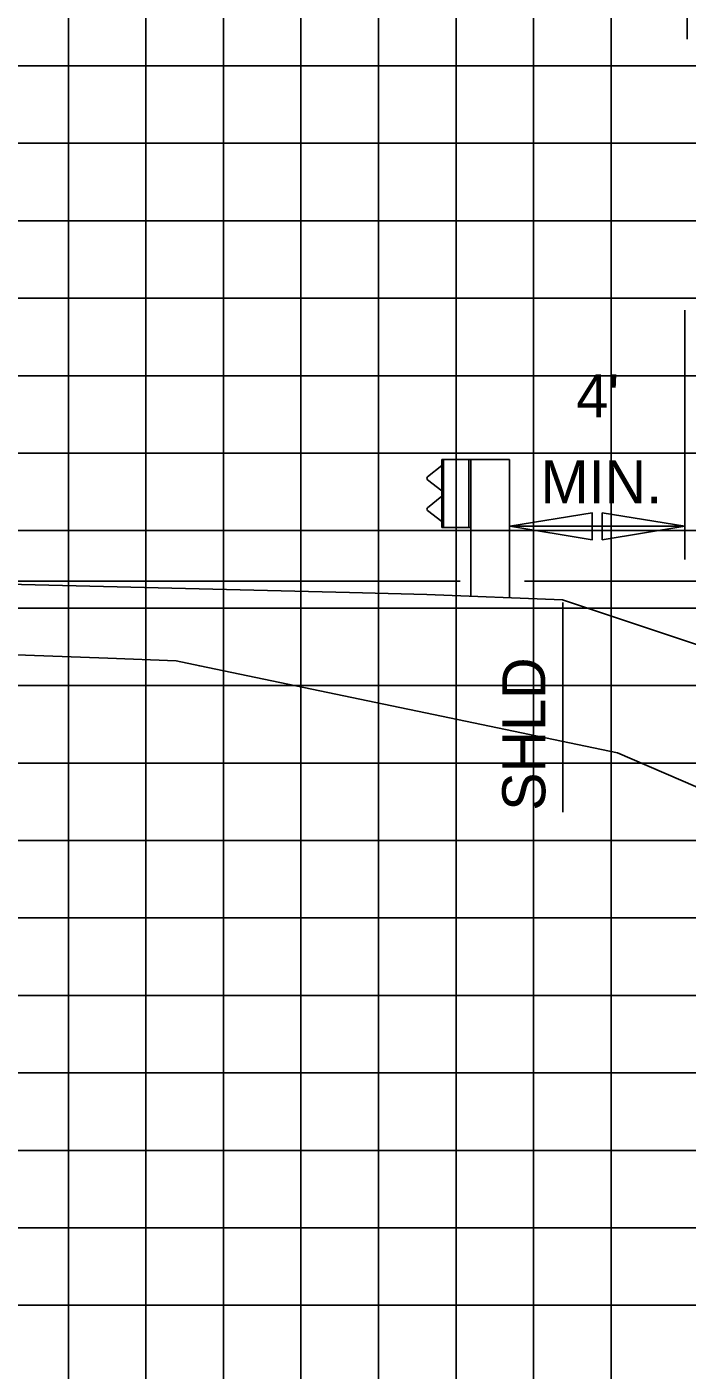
# Model space of a CAD drawing. Extents: x 2193008 to 2198143, y 1236112 to 1237864.
# Drawn here: x 2195451.71 to 2195468.75, y 1237175.43 to 1237210.11 of the extents above; entities that cross this region are included whole.
import ezdxf

# ---------------------------------------------------------------- set-up
doc = ezdxf.new("R2010")
doc.units = 0
for name, color, linetype in [('3', 7, 'Continuous'), ('60', 7, 'Continuous'), ('GSDIMS', 7, 'Continuous'), ('Level 1', 7, 'Continuous'), ('Level 55', 7, 'Continuous'), ('Level 61', 7, 'Continuous'), ('M-ROADS', 7, 'Continuous')]:
    doc.layers.add(name, color=color, linetype=linetype)

msp = doc.modelspace()

# ---------------------------------------------------------------- linework, layer by layer
at = {"layer": '3'}
msp.add_line((2195468.685, 1237196.363), (2195468.685, 1237202.8), dxfattribs=at)
at = {"layer": '60'}
msp.add_lwpolyline([(2195388.783, 1237193.146), (2195389.871, 1237193.142), (2195390.033, 1237193.15), (2195400.033, 1237193.607), (2195412.033, 1237194.155), (2195424.033, 1237194.703), (2195436.033, 1237195.252), (2195448.033, 1237195.8), (2195460.033, 1237195.509), (2195462.033, 1237195.46), (2195465.533, 1237195.32), (2195498.642, 1237184.284)], dxfattribs=at)
at = {"layer": 'GSDIMS'}
for p, q in [((2195468.745, 1237209.793), (2195468.745, 1237211.535)), ((2195462.887, 1237195.8), (2195448.033, 1237195.8)), ((2195470.334, 1237195.8), (2195464.548, 1237195.8)), ((2195465.539, 1237189.836), (2195465.539, 1237195.251))]:
    msp.add_line(p, q, dxfattribs=at)
for points in [[(2195464.17, 1237197.218), (2195466.299, 1237196.87), (2195466.299, 1237197.565)], [(2195468.685, 1237197.218), (2195466.557, 1237196.87), (2195466.557, 1237197.565)]]:
    msp.add_lwpolyline(points, close=True, dxfattribs=at)
at = {"layer": 'Level 1'}
for p, q in [((2195462.414, 1237198.79), (2195462.048, 1237198.491)), ((2195462.414, 1237198.94), (2195462.414, 1237197.19)), ((2195464.164, 1237198.94), (2195462.414, 1237198.94)), ((2195462.464, 1237198.94), (2195462.464, 1237197.19)), ((2195463.114, 1237198.94), (2195463.114, 1237197.19)), ((2195463.164, 1237198.94), (2195463.164, 1237195.415)), ((2195464.164, 1237198.94), (2195464.164, 1237195.375)), ((2195462.049, 1237198.42), (2195462.414, 1237198.135)), ((2195462.414, 1237197.995), (2195462.048, 1237197.696)), ((2195462.049, 1237197.625), (2195462.414, 1237197.34)), ((2195463.164, 1237197.19), (2195462.414, 1237197.19))]:
    msp.add_line(p, q, dxfattribs=at)
for centre in [(2195462.083, 1237198.456), (2195462.083, 1237197.661)]:
    msp.add_arc(centre, 0.05, 135, 226.6208, dxfattribs=at)
at = {"layer": 'Level 61'}
msp.add_line((2195464.17, 1237197.218), (2195468.685, 1237197.218), dxfattribs=at)
at = {"layer": 'M-ROADS'}
for p, q in [((2195452.783, 1237163.106), (2195452.783, 1237223.106)), ((2195454.783, 1237163.106), (2195454.783, 1237223.106)), ((2195456.783, 1237163.106), (2195456.783, 1237223.106)), ((2195458.783, 1237163.106), (2195458.783, 1237223.106)), ((2195460.783, 1237163.106), (2195460.783, 1237223.106)), ((2195462.783, 1237163.106), (2195462.783, 1237223.106)), ((2195464.783, 1237163.106), (2195464.783, 1237223.106)), ((2195466.783, 1237163.106), (2195466.783, 1237223.106)), ((2195388.783, 1237209.106), (2195518.783, 1237209.106)), ((2195388.783, 1237207.106), (2195518.783, 1237207.106)), ((2195388.783, 1237205.106), (2195518.783, 1237205.106)), ((2195388.783, 1237203.106), (2195518.783, 1237203.106)), ((2195388.783, 1237201.106), (2195518.783, 1237201.106)), ((2195388.783, 1237199.106), (2195518.783, 1237199.106)), ((2195388.783, 1237197.106), (2195518.783, 1237197.106)), ((2195388.783, 1237195.106), (2195518.783, 1237195.106)), ((2195388.783, 1237193.106), (2195518.783, 1237193.106)), ((2195388.783, 1237191.106), (2195518.783, 1237191.106)), ((2195388.783, 1237189.106), (2195518.783, 1237189.106)), ((2195388.783, 1237187.106), (2195518.783, 1237187.106)), ((2195388.783, 1237185.106), (2195518.783, 1237185.106)), ((2195388.783, 1237183.106), (2195518.783, 1237183.106)), ((2195388.783, 1237181.106), (2195518.783, 1237181.106)), ((2195388.783, 1237179.106), (2195518.783, 1237179.106)), ((2195388.783, 1237177.106), (2195518.783, 1237177.106))]:
    msp.add_line(p, q, dxfattribs=at)
msp.add_lwpolyline([(2195447.18, 1237194.058), (2195453.801, 1237193.813), (2195455.56, 1237193.748), (2195456.172, 1237193.613), (2195466.949, 1237191.373), (2195471.031, 1237189.607)], dxfattribs=at)

# ---------------------------------------------------------------- texts
at = {"layer": 'Level 55'}
for s, p in [("4'", (2195465.885, 1237200.031)), ('MIN.', (2195464.966, 1237197.81))]:
    msp.add_text(s, height=1.1105, dxfattribs=at).set_placement(p)
msp.add_text('SHLD', height=1.1105, rotation=90, dxfattribs=at).set_placement((2195465.087, 1237189.872))

doc.saveas('drawing.dxf')
